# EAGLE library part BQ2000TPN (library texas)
CHARGE MANAGEMENT IC
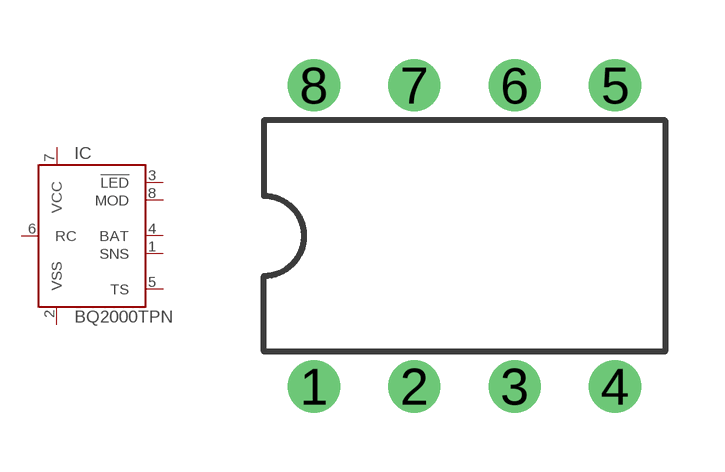
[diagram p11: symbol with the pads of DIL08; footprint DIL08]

Designator prefix IC

## BQ2000TPN (MF: TEXAS INSTRUMENT CONNECTORS; MPN: BQ2000TPN-B5; OC_FARNELL: unknown; OC_NEWARK: 74C7505)  [DIL08]
1  SNS  in
2  VSS  pwr
3  !LED  out
4  BAT  in
5  TS  in
6  RC  in
7  VCC  in
8  MOD  out

## Footprint DIL08 (pad centres in mm)
Dual In Line Package
drill 0.813 pad 1.27 round: 1 -3.81,-3.81; 2 -1.27,-3.81; 3 1.27,-3.81; 4 3.81,-3.81; 5 3.81,3.81; 6 1.27,3.81; 7 -1.27,3.81; 8 -3.81,3.81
